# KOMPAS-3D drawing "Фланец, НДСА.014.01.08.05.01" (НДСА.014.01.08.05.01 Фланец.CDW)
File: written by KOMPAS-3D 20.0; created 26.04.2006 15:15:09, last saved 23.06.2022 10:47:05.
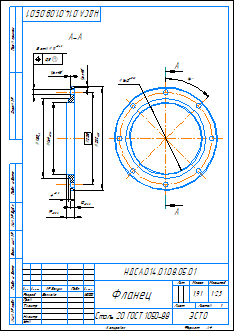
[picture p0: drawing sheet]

Sheet 1: A4, portrait

Document properties: Автор: Устинов А.В.; Организация: Эсто-вакуум; Полное имя файла: НДСА.014.01.08.05.01 Фланец.m3d; 246363213762: <item xmlns="http://appius.ru/pdm" xmlns:xs="http://www.w3.org/2001/XMLSchema" xmlns:xsi="http://www.w3.org/2001/XMLSchema-instance" xsi:type="item">  <element xmlns:d2p1="http://v8.1c.ru/8.1/data/enterprise/current-config" xsi:type="d2p1:CatalogRef.aps_Элемен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; PLM_CDWXDTO: <item xmlns="http://appius.ru/pdm" xmlns:xs="http://www.w3.org/2001/XMLSchema" xmlns:xsi="http://www.w3.org/2001/XMLSchema-instance" xsi:type="item">  <element xmlns:d2p1="http://v8.1c.ru/8.1/data/enterprise/current-config" xsi:type="d2p1:CatalogRef.aps_Элемен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; Масса: 1.90963

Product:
- Part/product: Фланец  | designation НДСА.014.01.08.05.01
    Материал: Сталь 20 ГОСТ 1050-88 (density 7859 kg/m3)
    Масса: 1.90963

Title block, sheet 1: Наименование: Фланец; designation: НДСА.014.01.08.05.01; Материал: Сталь 20 ГОСТ 1050-88; Масса: 1,91; scale: 1:2,5; Количество листов документа: 1; organisation: ЭСТО; Форматы листов документа: A4; stored path: D:\WorkPDM\Устинов А.В\adef4302-e6d0-4e78-a7d0-57c469fcab05\УКРД.789.01.05.00.02 Фланец.cdw; Разработал: Волкова; Разработал, date: 16.01.2020

Views: Вид 1, Разрез А-А
Referenced files in E:\НДСА.014.01.08.00.00 Гидроподъемник\: НДСА.014.01.08.05.01 Фланец.m3d
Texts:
  НДСА.014.01.08.05.01 Фланец
Dimensions and other numbers on the sheet: 160; 1; 164; 232; 19; 208; 10; 4; 180; 1,6; 8 отв.; 11; 1:2,5; 1,91; 16.01.2020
